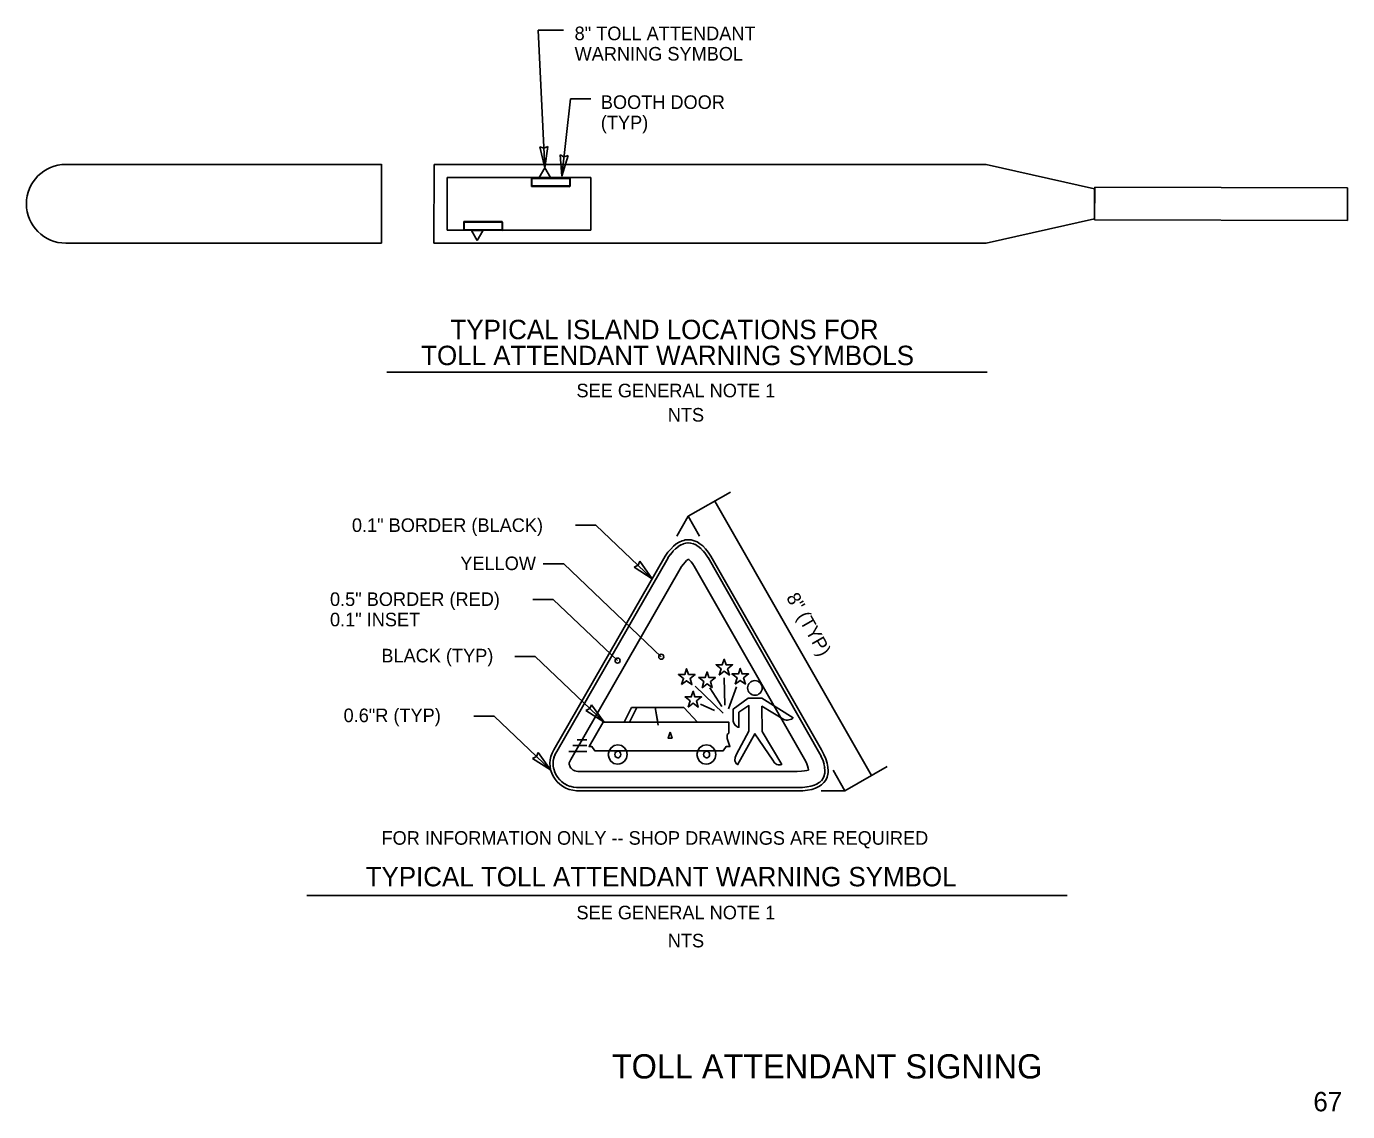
# Model space of a CAD drawing. Extents: x 53068 to 53703, y 9291 to 9710.
# Drawn here: x 53422.9 to 53695.3, y 9301.3 to 9525.1 of the extents above; entities that cross this region are included whole.
import ezdxf

# ---------------------------------------------------------------- set-up
doc = ezdxf.new("R2010")
doc.units = 0
for name, color, linetype in [('LeaderLine_dp', 7, 'Continuous'), ('RoadwayMisc', 7, 'Continuous'), ('SignPanel', 7, 'Continuous'), ('TextAlert', 7, 'Continuous'), ('TextDetails', 7, 'Continuous'), ('TextLabel', 7, 'Continuous'), ('TextMisc', 7, 'Continuous'), ('TextShtNo', 7, 'Continuous')]:
    doc.layers.add(name, color=color, linetype=linetype)

msp = doc.modelspace()

# ---------------------------------------------------------------- linework, layer by layer
at = {"layer": 'LeaderLine_dp'}
for p, q in [((53528.36, 9524.3), (53533.6, 9524.31)), ((53529.76, 9495.92), (53528.36, 9524.3)), ((53533.27, 9494.19), (53535.04, 9510.14)), ((53535.04, 9510.14), (53539.25, 9510.14)), ((53529.56, 9499.94), (53528.74, 9500.23)), ((53528.74, 9500.23), (53529.76, 9495.92)), ((53530.38, 9500.31), (53529.56, 9499.94)), ((53529.76, 9495.92), (53530.38, 9500.31)), ((53533.71, 9498.18), (53532.94, 9498.6)), ((53532.94, 9498.6), (53533.27, 9494.19)), ((53533.27, 9494.19), (53534.58, 9498.42)), ((53534.58, 9498.42), (53533.71, 9498.18)), ((53559.32, 9424.04), (53568.03, 9429.01)), ((53597.12, 9370.57), (53564.81, 9427.18)), ((53540.3, 9422.23), (53536.08, 9422.23)), ((53551.92, 9411.16), (53540.3, 9422.23)), ((53533.67, 9414.24), (53529.45, 9414.24)), ((53553.78, 9395.08), (53533.67, 9414.24)), ((53548.19, 9413.55), (53549.01, 9413.93)), ((53551.92, 9411.16), (53548.19, 9413.55)), ((53549.01, 9413.93), (53549.33, 9414.75)), ((53549.33, 9414.75), (53551.92, 9411.16)), ((53531.5, 9406.91), (53527.29, 9406.91)), ((53544.77, 9394.28), (53531.5, 9406.91)), ((53527.8, 9395.11), (53523.58, 9395.11)), ((53541.98, 9381.59), (53527.8, 9395.11)), ((53538.25, 9383.99), (53539.07, 9384.37)), ((53541.98, 9381.59), (53538.25, 9383.99)), ((53539.07, 9384.37), (53539.39, 9385.18)), ((53539.39, 9385.18), (53541.98, 9381.59)), ((53519.34, 9382.8), (53515.12, 9382.8)), ((53530.96, 9371.73), (53519.34, 9382.8)), ((53528.05, 9374.5), (53528.37, 9375.31)), ((53528.37, 9375.31), (53530.96, 9371.73)), ((53527.23, 9374.12), (53528.05, 9374.5)), ((53530.96, 9371.73), (53527.23, 9374.12)), ((53591.62, 9367.44), (53600.34, 9372.41))]:
    msp.add_line(p, q, dxfattribs=at)
for centre in [(53544.77, 9394.28), (53553.78, 9395.08)]:
    msp.add_circle(centre, 0.522, dxfattribs=at)
at = {"layer": 'RoadwayMisc'}
for p, q in [((53430.99, 9496.61), (53496.1, 9496.61)), ((53496.1, 9496.64), (53496.06, 9480.37)), ((53506.94, 9496.61), (53506.9, 9480.35)), ((53506.94, 9496.61), (53620.77, 9496.61)), ((53528.6, 9493.92), (53529.76, 9495.92)), ((53529.76, 9495.92), (53530.91, 9493.91)), ((53620.77, 9496.61), (53643.13, 9491.57)), ((53509.65, 9493.9), (53509.62, 9483.06)), ((53509.65, 9493.9), (53539.25, 9493.9)), ((53527.01, 9493.7), (53527.01, 9492.01)), ((53534.92, 9493.68), (53527.01, 9493.7)), ((53527.08, 9493.91), (53527.08, 9492.22)), ((53534.99, 9493.89), (53527.08, 9493.91)), ((53530.91, 9493.91), (53528.6, 9493.92)), ((53534.92, 9491.99), (53534.92, 9493.68)), ((53534.99, 9492.19), (53534.99, 9493.89)), ((53539.25, 9493.9), (53539.23, 9483.06)), ((53527.01, 9492.01), (53534.92, 9491.99)), ((53527.08, 9492.22), (53534.99, 9492.19)), ((53643.13, 9491.57), (53643.13, 9485.38)), ((53643.17, 9491.93), (53643.15, 9485.18)), ((53695.31, 9491.79), (53643.17, 9491.93)), ((53695.29, 9485.02), (53695.31, 9491.79)), ((53513.05, 9483.15), (53513.05, 9484.85)), ((53513.05, 9484.85), (53520.96, 9484.83)), ((53513.12, 9483.01), (53513.12, 9484.71)), ((53513.12, 9484.71), (53521.03, 9484.69)), ((53520.96, 9484.83), (53520.96, 9483.13)), ((53521.03, 9484.69), (53521.03, 9482.99)), ((53620.77, 9480.34), (53643.13, 9485.38)), ((53643.15, 9485.18), (53695.29, 9485.02)), ((53509.62, 9483.06), (53539.23, 9483.06)), ((53520.96, 9483.13), (53513.05, 9483.15)), ((53521.03, 9482.99), (53513.12, 9483.01)), ((53516.98, 9482.93), (53514.66, 9482.94)), ((53514.66, 9482.94), (53515.81, 9480.93)), ((53515.81, 9480.93), (53516.98, 9482.93)), ((53430.99, 9480.34), (53496.11, 9480.34)), ((53506.9, 9480.35), (53620.77, 9480.34))]:
    msp.add_line(p, q, dxfattribs=at)
msp.add_arc((53430.99, 9488.48), 8.13, 89.999, 269.999, dxfattribs=at)
at = {"layer": 'SignPanel'}
for p, q in [((53559.32, 9424.04), (53556.96, 9419.94)), ((53561.66, 9419.94), (53559.32, 9424.04)), ((53557.48, 9418.72), (53556.88, 9418.35)), ((53558.09, 9418.98), (53557.48, 9418.72)), ((53558.4, 9419.08), (53558.09, 9418.98)), ((53558.71, 9419.15), (53558.4, 9419.08)), ((53559.32, 9419.21), (53558.71, 9419.15)), ((53559.94, 9419.17), (53559.32, 9419.21)), ((53560.55, 9419.01), (53559.94, 9419.17)), ((53561.16, 9418.76), (53560.55, 9419.01)), ((53561.75, 9418.39), (53561.16, 9418.76)), ((53555.15, 9416.62), (53554.6, 9415.84)), ((53555.72, 9417.29), (53555.15, 9416.62)), ((53555.7, 9416.24), (53555.15, 9415.45)), ((53556.23, 9416.86), (53555.66, 9416.19)), ((53556.29, 9417.87), (53555.72, 9417.29)), ((53556.76, 9417.4), (53556.19, 9416.82)), ((53556.88, 9418.35), (53556.29, 9417.87)), ((53557.3, 9417.83), (53556.71, 9417.35)), ((53557.83, 9418.15), (53557.23, 9417.78)), ((53558.36, 9418.37), (53557.75, 9418.11)), ((53558.6, 9418.44), (53558.29, 9418.34)), ((53558.85, 9418.5), (53558.55, 9418.43)), ((53559.38, 9418.54), (53558.77, 9418.48)), ((53559.89, 9418.5), (53559.28, 9418.54)), ((53560.39, 9418.36), (53559.77, 9418.52)), ((53560.9, 9418.14), (53560.29, 9418.4)), ((53561.4, 9417.82), (53560.8, 9418.19)), ((53561.92, 9417.4), (53561.34, 9417.86)), ((53562.34, 9417.92), (53561.75, 9418.39)), ((53562.44, 9416.86), (53561.86, 9417.45)), ((53562.91, 9417.33), (53562.34, 9417.92)), ((53562.96, 9416.23), (53562.4, 9416.91)), ((53563.47, 9416.65), (53562.91, 9417.33)), ((53563.44, 9415.47), (53562.91, 9416.28)), ((53564, 9415.84), (53563.47, 9416.65)), ((53554.6, 9415.84), (53531.64, 9375.85)), ((53555.18, 9415.5), (53532.22, 9375.51)), ((53557.98, 9413.69), (53535.12, 9373.86)), ((53558.33, 9414.18), (53557.98, 9413.69)), ((53558.67, 9414.58), (53558.33, 9414.18)), ((53558.98, 9414.89), (53558.67, 9414.58)), ((53559.2, 9415.08), (53558.98, 9414.89)), ((53559.34, 9415.16), (53559.2, 9415.08)), ((53559.35, 9415.17), (53559.34, 9415.16)), ((53559.44, 9415.11), (53559.35, 9415.17)), ((53559.65, 9414.94), (53559.44, 9415.11)), ((53559.93, 9414.66), (53559.65, 9414.94)), ((53560.24, 9414.29), (53559.93, 9414.66)), ((53560.58, 9413.75), (53560.24, 9414.29)), ((53583.31, 9373.94), (53560.58, 9413.75)), ((53586.23, 9375.54), (53563.42, 9415.51)), ((53586.81, 9375.87), (53564, 9415.84)), ((53566.56, 9383.47), (53560.76, 9389.04)), ((53560.76, 9389.04), (53566.56, 9383.47)), ((53566.88, 9385.08), (53566.77, 9390.7)), ((53566.77, 9390.7), (53566.88, 9385.08)), ((53567.65, 9384.31), (53569.26, 9388.84)), ((53569.26, 9388.84), (53567.65, 9384.31)), ((53566.24, 9384.82), (53563.81, 9388.65)), ((53563.81, 9388.65), (53566.24, 9384.82)), ((53548.76, 9384.6), (53547.25, 9381.59)), ((53558.42, 9384.6), (53548.76, 9384.6)), ((53552.54, 9384.6), (53553.16, 9380.95)), ((53561.27, 9381.59), (53558.42, 9384.6)), ((53564.78, 9383.99), (53561.88, 9385.32)), ((53561.88, 9385.32), (53564.78, 9383.99)), ((53541.77, 9381.59), (53538.88, 9376.56)), ((53547.25, 9381.59), (53541.77, 9381.59)), ((53561.27, 9381.59), (53547.25, 9381.59)), ((53547.25, 9381.59), (53561.27, 9381.59)), ((53561.27, 9381.59), (53567.68, 9381.59)), ((53567.68, 9379.34), (53567.68, 9381.59)), ((53538.4, 9377.97), (53536.43, 9377.97)), ((53567.37, 9379.03), (53567.68, 9379.34)), ((53567.37, 9378.21), (53567.37, 9379.03)), ((53567.92, 9376.56), (53567.37, 9378.21)), ((53531.27, 9375.19), (53531.01, 9374.51)), ((53531.64, 9375.85), (53531.27, 9375.19)), ((53532.22, 9375.52), (53531.85, 9374.86)), ((53538.42, 9375.56), (53534.72, 9375.56)), ((53538.42, 9376.79), (53535.55, 9376.79)), ((53539.48, 9376.56), (53538.88, 9376.56)), ((53540.07, 9375.7), (53539.48, 9376.56)), ((53542.86, 9375.7), (53540.07, 9375.7)), ((53560.94, 9375.7), (53546.97, 9375.7)), ((53566.55, 9375.7), (53565.24, 9375.7)), ((53566.55, 9375.7), (53567.13, 9376.56)), ((53567.13, 9376.56), (53567.92, 9376.56)), ((53586.73, 9374.6), (53586.22, 9375.55)), ((53587.32, 9374.91), (53586.81, 9375.87)), ((53530.84, 9373.81), (53530.79, 9373.1)), ((53530.79, 9373.1), (53530.83, 9372.41)), ((53530.83, 9372.41), (53530.96, 9371.73)), ((53531.01, 9374.51), (53530.84, 9373.81)), ((53531.51, 9373.75), (53531.45, 9373.05)), ((53531.45, 9373.15), (53531.5, 9372.45)), ((53531.66, 9374.35), (53531.49, 9373.65)), ((53531.49, 9372.53), (53531.62, 9371.85)), ((53531.9, 9374.95), (53531.63, 9374.27)), ((53534.81, 9373.17), (53534.8, 9373.08)), ((53534.8, 9373.08), (53534.81, 9372.91)), ((53534.84, 9373.32), (53534.81, 9373.17)), ((53534.81, 9372.91), (53534.85, 9372.71)), ((53534.9, 9373.48), (53534.84, 9373.32)), ((53534.85, 9372.71), (53534.9, 9372.55)), ((53535.12, 9373.86), (53534.9, 9373.48)), ((53534.9, 9372.55), (53534.98, 9372.37)), ((53583.7, 9373.19), (53583.31, 9373.94)), ((53583.95, 9372.6), (53583.7, 9373.19)), ((53584.1, 9372.13), (53583.95, 9372.6)), ((53587.08, 9373.74), (53586.7, 9374.65)), ((53587.35, 9372.93), (53587.07, 9373.79)), ((53587.7, 9374), (53587.32, 9374.91)), ((53587.48, 9372.2), (53587.33, 9373.01)), ((53587.98, 9373.14), (53587.7, 9374)), ((53588.14, 9372.33), (53587.98, 9373.14)), ((53530.96, 9371.73), (53531.18, 9371.06)), ((53531.18, 9371.06), (53531.48, 9370.43)), ((53531.48, 9370.43), (53531.86, 9369.83)), ((53531.59, 9371.93), (53531.81, 9371.27)), ((53531.78, 9371.35), (53532.08, 9370.71)), ((53531.86, 9369.83), (53532.32, 9369.28)), ((53532.04, 9370.78), (53532.42, 9370.19)), ((53532.37, 9370.26), (53532.83, 9369.71)), ((53532.78, 9369.76), (53533.3, 9369.27)), ((53534.98, 9372.37), (53535.09, 9372.2)), ((53535.09, 9372.2), (53535.24, 9372.02)), ((53535.24, 9372.02), (53535.41, 9371.86)), ((53535.41, 9371.86), (53535.59, 9371.72)), ((53535.59, 9371.72), (53535.79, 9371.61)), ((53535.79, 9371.61), (53535.97, 9371.54)), ((53535.97, 9371.54), (53536.24, 9371.48)), ((53536.24, 9371.48), (53536.55, 9371.44)), ((53536.55, 9371.44), (53581.83, 9371.44)), ((53581.83, 9371.44), (53582.69, 9371.45)), ((53582.69, 9371.45), (53583.33, 9371.52)), ((53583.33, 9371.52), (53583.82, 9371.62)), ((53583.82, 9371.62), (53584.15, 9371.72)), ((53584.17, 9371.79), (53584.1, 9372.13)), ((53584.15, 9371.72), (53584.17, 9371.73)), ((53584.17, 9371.73), (53584.17, 9371.79)), ((53586.79, 9369.51), (53587.16, 9370.03)), ((53587.1, 9369.93), (53587.37, 9370.51)), ((53587.33, 9370.4), (53587.49, 9371.04)), ((53587.53, 9371.53), (53587.47, 9372.28)), ((53587.48, 9370.97), (53587.53, 9371.31)), ((53587.52, 9371.24), (53587.53, 9371.6)), ((53587.7, 9369.65), (53587.97, 9370.23)), ((53587.97, 9370.23), (53588.14, 9370.88)), ((53588.2, 9371.58), (53588.14, 9372.33)), ((53588.14, 9370.88), (53588.19, 9371.22)), ((53588.19, 9371.22), (53588.2, 9371.58)), ((53591.62, 9367.44), (53589.21, 9371.66)), ((53532.32, 9369.28), (53532.84, 9368.79)), ((53532.84, 9368.79), (53533.42, 9368.36)), ((53533.23, 9369.32), (53533.82, 9368.89)), ((53533.42, 9368.36), (53534.07, 9367.99)), ((53533.75, 9368.94), (53534.39, 9368.57)), ((53534.07, 9367.99), (53534.76, 9367.72)), ((53534.31, 9368.61), (53535, 9368.34)), ((53534.76, 9367.72), (53535.51, 9367.54)), ((53534.92, 9368.37), (53535.67, 9368.18)), ((53535.51, 9367.54), (53536.29, 9367.44)), ((53535.6, 9368.2), (53536.38, 9368.1)), ((53536.29, 9368.1), (53581.87, 9368.1)), ((53536.29, 9367.44), (53581.87, 9367.44)), ((53581.86, 9368.1), (53582.93, 9368.12)), ((53581.87, 9367.44), (53582.94, 9367.46)), ((53582.87, 9368.12), (53583.85, 9368.23)), ((53582.94, 9367.46), (53583.92, 9367.56)), ((53583.79, 9368.22), (53584.67, 9368.39)), ((53583.92, 9367.56), (53584.8, 9367.73)), ((53584.6, 9368.37), (53585.38, 9368.61)), ((53584.8, 9367.73), (53585.58, 9367.98)), ((53585.3, 9368.58), (53585.99, 9368.89)), ((53585.58, 9367.98), (53586.26, 9368.29)), ((53585.89, 9368.84), (53586.48, 9369.23)), ((53586.26, 9368.29), (53586.85, 9368.68)), ((53586.39, 9369.16), (53586.87, 9369.61)), ((53586.75, 9367.44), (53591.62, 9367.44)), ((53586.85, 9368.68), (53587.33, 9369.13)), ((53587.33, 9369.13), (53587.7, 9369.65))]:
    msp.add_line(p, q, dxfattribs=at)
for points in [[(53565.72, 9391.28), (53566.13, 9392.57), (53565.08, 9393.41), (53566.36, 9393.41), (53566.77, 9394.56), (53567.15, 9393.41), (53568.49, 9393.41), (53567.44, 9392.57), (53567.82, 9391.31), (53566.77, 9392.09)], [(53557.97, 9389.33), (53558.37, 9390.62), (53557.32, 9391.42), (53558.64, 9391.42), (53559.01, 9392.6), (53559.41, 9391.42), (53560.76, 9391.42), (53559.71, 9390.62), (53560.08, 9389.35), (53559.01, 9390.13)], [(53562.18, 9388.68), (53562.58, 9389.97), (53561.51, 9390.8), (53562.83, 9390.8), (53563.23, 9391.95), (53563.6, 9390.8), (53564.95, 9390.8), (53563.9, 9389.97), (53564.27, 9388.71), (53563.23, 9389.48)], [(53569, 9389.41), (53569.43, 9390.7), (53568.36, 9391.52), (53569.67, 9391.52), (53570.08, 9392.68), (53570.45, 9391.52), (53571.79, 9391.52), (53570.74, 9390.7), (53571.12, 9389.45), (53570.08, 9390.21)], [(53573.08, 9390.16), (53573.4, 9390.13), (53573.67, 9390.04), (53573.92, 9389.9), (53574.15, 9389.72), (53574.33, 9389.49), (53574.47, 9389.24), (53574.56, 9388.97), (53574.59, 9388.65), (53574.56, 9388.35), (53574.47, 9388.07), (53574.33, 9387.8), (53574.15, 9387.58), (53573.92, 9387.4), (53573.67, 9387.25), (53573.4, 9387.16), (53573.08, 9387.12), (53572.79, 9387.16), (53572.52, 9387.25), (53572.26, 9387.4), (53572.03, 9387.58), (53571.84, 9387.8), (53571.71, 9388.07), (53571.62, 9388.35), (53571.58, 9388.65), (53571.62, 9388.97), (53571.71, 9389.24), (53571.84, 9389.49), (53572.03, 9389.72), (53572.26, 9389.9), (53572.52, 9390.04), (53572.79, 9390.13)], [(53559.3, 9384.68), (53559.71, 9385.97), (53558.67, 9386.8), (53559.95, 9386.8), (53560.36, 9387.96), (53560.73, 9386.8), (53562.1, 9386.8), (53561.02, 9385.97), (53561.4, 9384.71), (53560.36, 9385.49)], [(53574.56, 9379.63), (53574.54, 9384.87), (53579.04, 9382.16), (53579.26, 9382.07), (53579.5, 9382.02), (53579.78, 9382.02), (53580.06, 9382.05), (53580.35, 9382.12), (53580.61, 9382.21), (53580.83, 9382.34), (53580.97, 9382.48), (53574.48, 9386.54), (53571.72, 9386.54), (53568.63, 9384.28), (53568.63, 9381.76), (53568.73, 9381.35), (53568.99, 9380.95), (53569.36, 9380.67), (53569.58, 9380.58), (53569.78, 9380.55), (53569.78, 9383.63), (53571.85, 9385), (53571.85, 9379.72), (53569.27, 9374.96), (53569.03, 9374.3), (53568.97, 9373.71), (53569.02, 9373.46), (53569.12, 9373.22), (53569.27, 9373.01), (53569.49, 9372.81), (53573.08, 9379.18), (53576.76, 9373.75), (53577.16, 9373.2), (53577.39, 9373.02), (53577.61, 9372.88), (53577.87, 9372.8), (53578.11, 9372.77), (53578.37, 9372.8), (53578.61, 9372.87)], [(53547.62, 9384.6), (53546.12, 9381.59), (53547.25, 9381.59), (53548.76, 9384.6)], [(53548.76, 9384.6), (53547.25, 9381.59), (53553.05, 9381.59), (53552.54, 9384.6)], [(53558.42, 9384.6), (53552.54, 9384.6), (53553.05, 9381.59), (53561.27, 9381.59)], [(53547.25, 9381.59), (53541.77, 9381.59), (53538.88, 9376.56), (53539.48, 9376.56), (53540.07, 9375.7), (53542.86, 9375.7), (53546.97, 9375.7), (53560.94, 9375.7), (53565.24, 9375.7), (53566.55, 9375.7), (53567.13, 9376.56), (53567.92, 9376.56), (53567.37, 9378.21), (53567.37, 9379.03), (53567.68, 9379.34), (53567.68, 9381.59)], [(53555.6, 9379.52), (53556, 9378.32), (53555.17, 9378.32)], [(53544.81, 9376.91), (53545.59, 9376.74), (53546.19, 9376.29), (53546.6, 9375.68), (53546.75, 9374.91), (53546.6, 9374.17), (53546.21, 9373.55), (53545.67, 9373.14), (53545.25, 9372.99), (53544.75, 9372.92), (53544.01, 9373.09), (53543.39, 9373.54), (53543, 9374.15), (53542.82, 9374.91), (53543, 9375.7), (53543.41, 9376.3), (53544.03, 9376.75)], [(53544.82, 9375.58), (53545.06, 9375.53), (53545.25, 9375.38), (53545.39, 9375.18), (53545.44, 9374.91), (53545.39, 9374.66), (53545.25, 9374.45), (53545.06, 9374.3), (53544.95, 9374.26), (53544.82, 9374.24), (53544.58, 9374.3), (53544.37, 9374.45), (53544.24, 9374.66), (53544.18, 9374.91), (53544.24, 9375.18), (53544.37, 9375.38), (53544.58, 9375.53)], [(53563.1, 9376.91), (53563.88, 9376.74), (53564.48, 9376.29), (53564.89, 9375.68), (53565.03, 9374.91), (53564.89, 9374.17), (53564.5, 9373.55), (53563.96, 9373.14), (53563.54, 9372.99), (53563.04, 9372.92), (53562.3, 9373.09), (53561.68, 9373.54), (53561.29, 9374.15), (53561.11, 9374.91), (53561.29, 9375.7), (53561.69, 9376.3), (53562.32, 9376.75)], [(53563.13, 9375.58), (53563.36, 9375.53), (53563.55, 9375.38), (53563.69, 9375.18), (53563.74, 9374.91), (53563.69, 9374.66), (53563.55, 9374.45), (53563.36, 9374.3), (53563.25, 9374.26), (53563.13, 9374.24), (53562.88, 9374.3), (53562.68, 9374.45), (53562.54, 9374.66), (53562.48, 9374.91), (53562.54, 9375.18), (53562.68, 9375.38), (53562.88, 9375.53)]]:
    msp.add_lwpolyline(points, close=True, dxfattribs=at)
at = {"layer": 'TextDetails'}
for p, q in [((53497.17, 9453.74), (53620.99, 9453.74)), ((53480.69, 9345.85), (53637.47, 9345.85))]:
    msp.add_line(p, q, dxfattribs=at)

# ---------------------------------------------------------------- texts
at = {"layer": 'TextAlert'}
msp.add_text('SEE GENERAL NOTE 1', height=2.8, dxfattribs=at).set_placement((53536.29, 9340.93))
at = {"layer": 'TextDetails'}
for s, height, p in [('TYPICAL ISLAND LOCATIONS FOR', 4, (53510.31, 9460.56)), ('TOLL ATTENDANT WARNING SYMBOLS', 4, (53504.26, 9455.21)), ('SEE GENERAL NOTE 1', 2.8, (53536.29, 9448.57)), ('NTS', 2.8, (53555.12, 9443.57)), ('FOR INFORMATION ONLY -- SHOP DRAWINGS ARE REQUIRED', 2.8, (53496.08, 9356.31)), ('TYPICAL TOLL ATTENDANT WARNING SYMBOL', 4, (53492.81, 9347.73)), ('NTS', 2.8, (53555.12, 9335.14))]:
    msp.add_text(s, height=height, dxfattribs=at).set_placement(p)
at = {"layer": 'TextLabel'}
for s, p in [('8" TOLL ATTENDANT', (53535.9, 9522.21)), ('WARNING SYMBOL', (53535.9, 9518.01)), ('BOOTH DOOR', (53541.31, 9508.04)), ('(TYP)', (53541.31, 9503.84)), ('0.1" BORDER (BLACK)', (53489.98, 9420.81)), ('YELLOW', (53512.33, 9412.94)), ('0.5" BORDER (RED)', (53485.46, 9405.55)), ('0.1" INSET', (53485.46, 9401.35)), ('BLACK (TYP)', (53496.05, 9393.91)), ('0.6"R (TYP)', (53488.26, 9381.59))]:
    msp.add_text(s, height=2.8, dxfattribs=at).set_placement(p)
msp.add_text('8" (TYP)', height=2.8, rotation=299.7146, dxfattribs=at).set_placement((53579.46, 9407.28))
at = {"layer": 'TextMisc'}
msp.add_text(' TOLL ATTENDANT SIGNING ', height=5, rotation=360, dxfattribs=at).set_placement((53541.72, 9308.11))
at = {"layer": 'TextShtNo'}
msp.add_text('67', height=4, rotation=360, dxfattribs=at).set_placement((53688.25, 9301.34))

doc.saveas('drawing.dxf')
